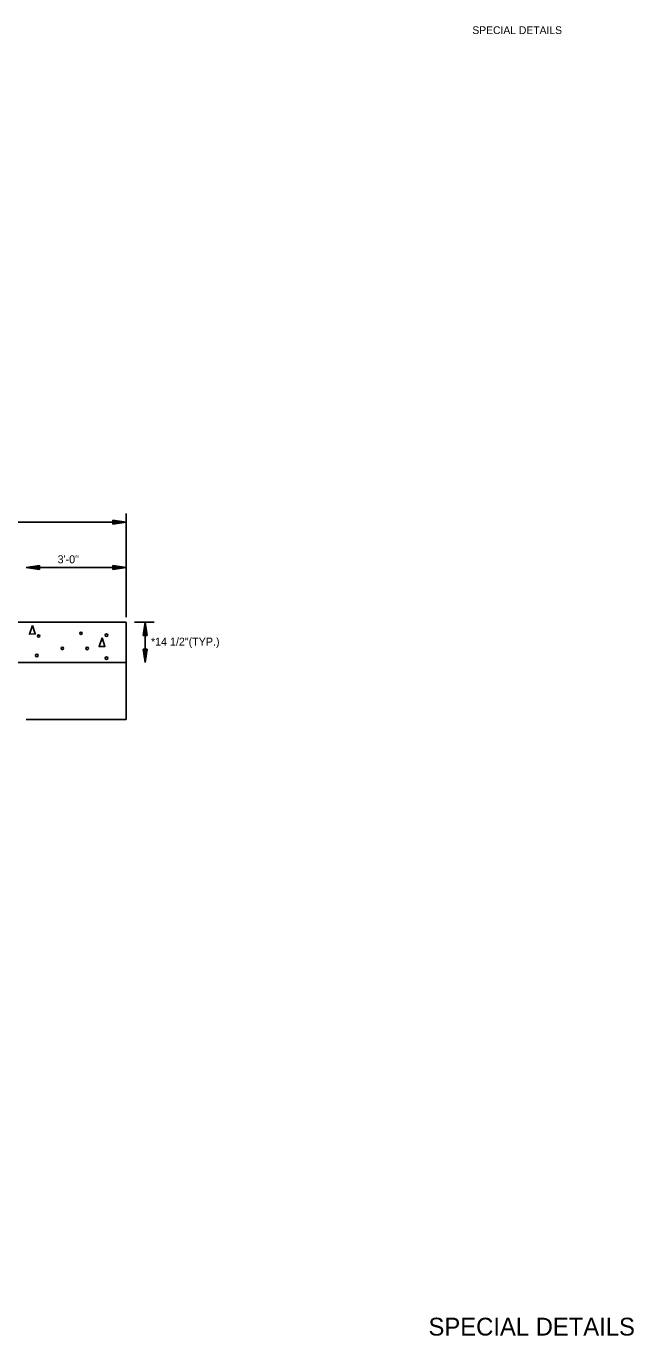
# Model space of a CAD drawing. Extents: x -149 to 1228740, y -106 to 152440.
# Drawn here: x -51.3 to -5.2, y 4 to 103.2 of the extents above; entities that cross this region are included whole.
import ezdxf

# ---------------------------------------------------------------- set-up
doc = ezdxf.new("R2010")
doc.units = 0
for name, color, linetype in [('R_Annotation', 7, 'Continuous'), ('R_Border', 7, 'Continuous'), ('R_Dimension', 7, 'Continuous'), ('R_Proposed Road', 7, 'Continuous'), ('R_Striping', 7, 'Continuous')]:
    doc.layers.add(name, color=color, linetype=linetype)

msp = doc.modelspace()

# ---------------------------------------------------------------- linework, layer by layer
at = {"layer": 'R_Dimension'}
for p, q in [((-85.402, 65.608), (-43.711, 65.608)), ((-44.72, 65.759), (-43.71, 65.607)), ((-44.72, 65.759), (-44.72, 65.456)), ((-44.72, 65.734), (-43.879, 65.607)), ((-44.72, 65.708), (-44.053, 65.607)), ((-44.72, 65.683), (-44.22, 65.607)), ((-44.72, 65.658), (-44.392, 65.607)), ((-44.72, 65.633), (-44.561, 65.607)), ((-44.72, 65.456), (-43.71, 65.607)), ((-44.72, 65.559), (-44.392, 65.607)), ((-44.72, 65.506), (-44.053, 65.607)), ((-44.72, 65.481), (-43.879, 65.607)), ((-44.72, 65.532), (-44.22, 65.607)), ((-44.72, 65.585), (-44.561, 65.607)), ((-43.711, 58.412), (-43.711, 66.276)), ((-43.711, 58.412), (-43.711, 62.721)), ((-43.711, 58.412), (-43.711, 62.721)), ((-43.711, 62.177), (-51.291, 62.177)), ((-50.279, 62.328), (-51.29, 62.176)), ((-50.279, 62.024), (-51.29, 62.176)), ((-50.279, 62.302), (-51.121, 62.176)), ((-50.279, 62.05), (-51.121, 62.176)), ((-50.279, 62.277), (-50.949, 62.176)), ((-50.279, 62.075), (-50.949, 62.176)), ((-50.279, 62.252), (-50.779, 62.176)), ((-50.279, 62.1), (-50.779, 62.176)), ((-50.279, 62.227), (-50.608, 62.176)), ((-50.279, 62.128), (-50.608, 62.176)), ((-50.279, 62.201), (-50.438, 62.176)), ((-50.279, 62.153), (-50.438, 62.176)), ((-50.279, 62.024), (-50.279, 62.328)), ((-44.722, 62.328), (-43.711, 62.177)), ((-44.722, 62.328), (-44.722, 62.025)), ((-44.722, 62.303), (-43.88, 62.177)), ((-44.722, 62.278), (-44.055, 62.177)), ((-44.722, 62.252), (-44.221, 62.177)), ((-44.722, 62.227), (-44.393, 62.177)), ((-44.722, 62.202), (-44.563, 62.177)), ((-44.722, 62.025), (-43.711, 62.177)), ((-44.722, 62.129), (-44.393, 62.177)), ((-44.722, 62.076), (-44.055, 62.177)), ((-44.722, 62.05), (-43.88, 62.177)), ((-44.722, 62.101), (-44.221, 62.177)), ((-44.722, 62.154), (-44.563, 62.177)), ((-43.086, 58.034), (-41.577, 58.034)), ((-42.411, 57.024), (-42.259, 58.035)), ((-42.386, 57.024), (-42.259, 57.868)), ((-42.358, 57.024), (-42.259, 57.694)), ((-42.108, 57.024), (-42.259, 58.035)), ((-42.133, 57.024), (-42.259, 57.868)), ((-42.158, 57.024), (-42.259, 57.694)), ((-42.258, 58.034), (-42.258, 54.98)), ((-42.411, 57.024), (-42.108, 57.024)), ((-42.333, 57.024), (-42.259, 57.524)), ((-42.307, 57.024), (-42.259, 57.353)), ((-42.282, 57.024), (-42.259, 57.186)), ((-42.184, 57.024), (-42.259, 57.524)), ((-42.209, 57.024), (-42.259, 57.353)), ((-42.234, 57.024), (-42.259, 57.186)), ((-42.411, 55.991), (-42.259, 54.98)), ((-42.108, 55.991), (-42.411, 55.991)), ((-42.386, 55.991), (-42.259, 55.149)), ((-42.358, 55.991), (-42.259, 55.324)), ((-42.333, 55.991), (-42.259, 55.49)), ((-42.307, 55.991), (-42.259, 55.662)), ((-42.282, 55.991), (-42.259, 55.831)), ((-42.108, 55.991), (-42.259, 54.98)), ((-42.209, 55.991), (-42.259, 55.662)), ((-42.158, 55.991), (-42.259, 55.324)), ((-42.133, 55.991), (-42.259, 55.149)), ((-42.184, 55.991), (-42.259, 55.49)), ((-42.234, 55.991), (-42.259, 55.831))]:
    msp.add_line(p, q, dxfattribs=at)
at = {"layer": 'R_Proposed Road'}
for p, q in [((-89.192, 58.034), (-43.711, 58.034)), ((-43.711, 58.034), (-43.711, 54.98)), ((-81.612, 54.98), (-47.501, 54.98)), ((-51.291, 54.98), (-43.711, 54.98)), ((-43.711, 50.66), (-43.711, 54.98)), ((-51.291, 50.66), (-43.711, 50.66))]:
    msp.add_line(p, q, dxfattribs=at)
for points in [[(-50.805, 57.79), (-51.05, 57.12), (-50.605, 57.138), (-50.805, 57.79)], [(-45.521, 56.855), (-45.764, 56.183), (-45.319, 56.2), (-45.521, 56.855)]]:
    msp.add_lwpolyline(points, dxfattribs=at)
for centre in [(-50.349, 56.979), (-47.138, 57.18), (-45.199, 57.046), (-50.483, 55.507), (-48.543, 56.042), (-46.67, 56.042), (-45.199, 55.306)]:
    msp.add_circle(centre, 0.0947, dxfattribs=at)

# ---------------------------------------------------------------- texts
at = {"layer": 'R_Annotation'}
for s, height, p in [('3\'-0"', 0.6065, (-48.907, 62.493)), ('*14 1/2"(TYP.)', 0.60645, (-41.83, 56.251))]:
    msp.add_text(s, height=height, dxfattribs=at).set_placement(p)
at = {"layer": 'R_Border'}
msp.add_text('SPECIAL DETAILS', height=0.5862, dxfattribs=at).set_placement((-17.46, 102.598))
at = {"layer": 'R_Striping'}
msp.add_text('SPECIAL DETAILS', height=1.35, dxfattribs=at).set_placement((-20.787, 3.972))

doc.saveas('drawing.dxf')
